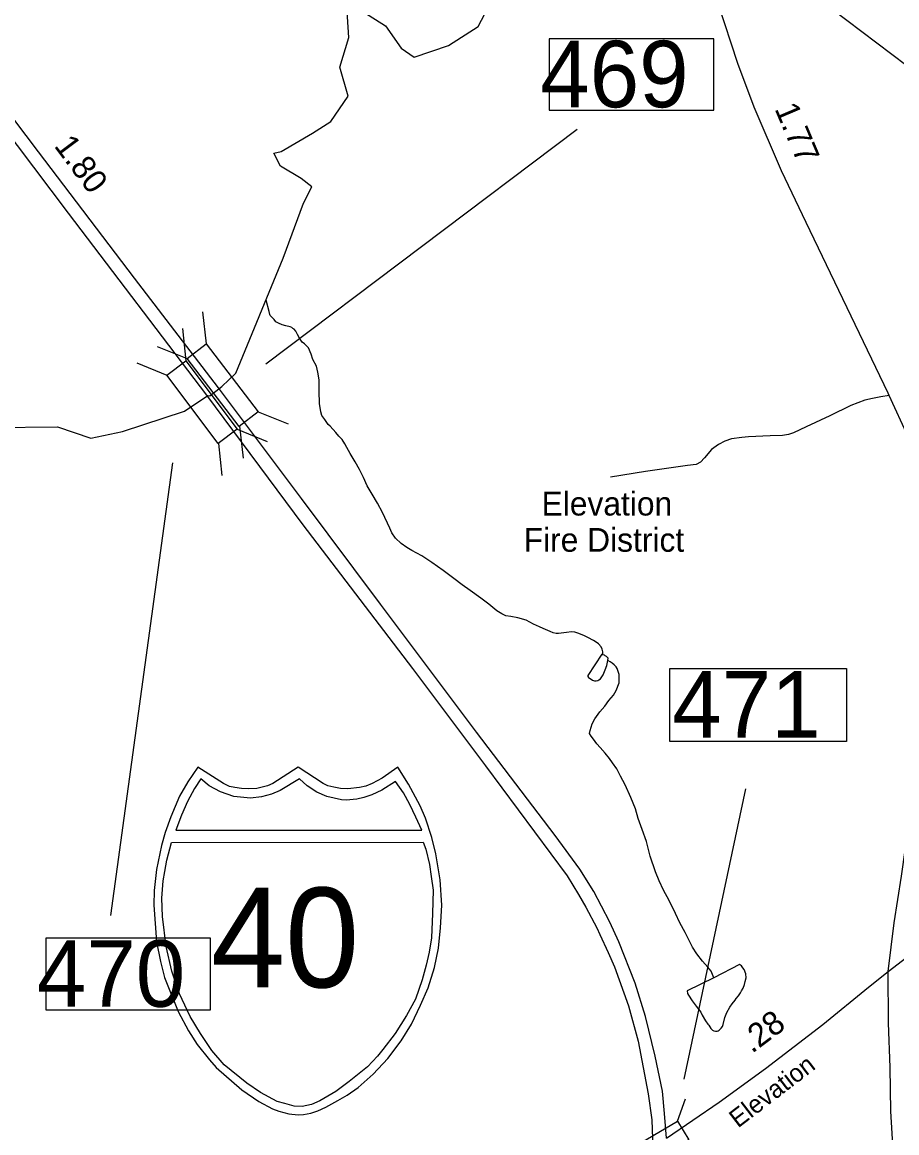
# Model space of a CAD drawing. Extents: x 2082433 to 2279600, y 546599 to 755198.
# Drawn here: x 2135647 to 2140251, y 619052 to 624897 of the extents above; entities that cross this region are included whole.
import ezdxf

# ---------------------------------------------------------------- set-up
doc = ezdxf.new("R2010")
doc.units = 0
for name, color, linetype in [('Exist Boundary Political Fire Districts Label', 7, 'Continuous'), ('Exist Hydrographic Creek Single Shore', 7, 'Continuous'), ('Exist Hydrographic Misc Water Feature', 7, 'Continuous'), ('Exist Hydrographic Pond Under 1500 Sq Ft', 7, 'Continuous'), ('Exist Road Non-System Type 51', 7, 'Continuous'), ('Exist Road Primary Interstate Divided Center Attributed', 7, 'Continuous'), ('Exist Road Primary Interstate Mileage Hundredths English Label', 7, 'Continuous'), ('Exist Road Primary Interstate Shield CELL', 7, 'Continuous'), ('Exist Road Primary Interstate Shield Number Label', 7, 'Continuous'), ('Exist Road Primary Interstate Structure Standard Bridge CELL', 7, 'Continuous'), ('Exist Road Primary Interstate Structure Standard Bridge Number Label', 7, 'Continuous'), ('Exist Road Secondary Mileage Hundredths English Label', 7, 'Continuous'), ('Exist Road Secondary Structure Standard Bridge CELL', 7, 'Continuous'), ('Exist Road Secondary Structure Standard Bridge Number Label', 7, 'Continuous'), ('Exist Road Secondary Type 51 Attributed', 7, 'Continuous'), ('Exist Road Secondary Type 51 Label', 7, 'Continuous')]:
    doc.layers.add(name, color=color, linetype=linetype)

msp = doc.modelspace()

# ---------------------------------------------------------------- linework, layer by layer
at = {"layer": 'Exist Hydrographic Creek Single Shore'}
for points in [[(2137354.5, 625008.9), (2137558.8, 624878.4), (2137641.5, 624761), (2137711, 624713.2), (2137891.2, 624775.6), (2138048.1, 624874.1), (2138139.1, 625049.5), (2138280.2, 625158.1), (2138629.2, 625334.7), (2139152.2, 625531.7), (2139303.2, 625645.9), (2139336.2, 625720.6), (2139444.1, 625770.9), (2139727, 625722.6), (2140152.1, 625776.2), (2140776.1, 625927.6), (2141376.1, 625938.4), (2141684.3, 626040.4), (2141909.2, 625983.4), (2142076.2, 626009.5), (2142267.3, 626159.8), (2142341.3, 626319), (2143015.3, 626371)], [(2137367.5, 624817.6), (2137354.5, 625008.9)], [(2135492, 622764.1), (2135833, 622767), (2136008, 622707.7), (2136175.1, 622743.8), (2136500.9, 622850.7), (2136623.6, 622932.6), (2136634.8, 622930.3), (2136697.4, 622980.7), (2136772.5, 623050.5), (2137021.1, 623655), (2137128, 623944.7), (2137171.8, 624030.5), (2137115.3, 624074), (2137006.6, 624139.2), (2136971.8, 624208.8), (2137011, 624217.5), (2137176.2, 624313.2), (2137271.9, 624374), (2137363.2, 624508.8), (2137319.7, 624661), (2137367.5, 624817.6)], [(2138703.9, 621567.3), (2138704.1, 621583.5), (2138700, 621597.5), (2138694.5, 621609.3), (2138680.1, 621625.2), (2138668, 621635.2), (2138653.7, 621643), (2138623.9, 621658.9), (2138607.9, 621667), (2138578, 621680.9), (2138555.8, 621686.6), (2138538, 621688.5), (2138511.8, 621684.7), (2138469.9, 621680.1), (2138458, 621680.3), (2138442, 621684.3), (2138426, 621690), (2138389.5, 621706.1), (2138369.7, 621716), (2138339.5, 621729.9), (2138299.9, 621749.6), (2138255.4, 621763.3), (2138220, 621769.1), (2138193.3, 621773.1), (2138171.2, 621782.9), (2138145.3, 621799), (2138103.3, 621834.5), (2138061.5, 621866.4), (2138004.7, 621906.3), (2137962.8, 621936.1), (2137918.7, 621969.9), (2137862.8, 622011.7), (2137804.3, 622053.3), (2137750.4, 622089.1), (2137698.1, 622116.9), (2137672.3, 622132.9), (2137642.3, 622154.5), (2137612.2, 622182.6), (2137592.1, 622210.4), (2137581.6, 622234.3), (2137543.5, 622316.3), (2137517.3, 622366.1), (2137489.2, 622413.7), (2137462.9, 622457.8), (2137444.7, 622501.6), (2137422.7, 622543.4), (2137400, 622583.3), (2137374.1, 622627.4), (2137355.7, 622659), (2137345.8, 622679.1), (2137332.1, 622701.1), (2137313.8, 622718.9), (2137297.6, 622738.8), (2137267.7, 622770.9), (2137257.2, 622780.5), (2137239.6, 622806.7), (2137225.1, 622826.8), (2137218.9, 622846.4), (2137212.8, 622890.3), (2137210.7, 622954.7), (2137210.5, 623014.3), (2137204.1, 623056.2), (2137196.1, 623086.3), (2137177.9, 623122.3), (2137168.1, 623150.1), (2137153.7, 623184.3), (2137133.6, 623204), (2137121.7, 623213.9), (2137107.2, 623234), (2137097.3, 623254.1), (2137087.5, 623271.8), (2137079.5, 623282), (2137071.7, 623285.5), (2137067.2, 623289.9), (2137057.3, 623293.8), (2137035.2, 623299.6), (2137015.3, 623305.4), (2136997.2, 623313.4), (2136983.1, 623321.2), (2136973.3, 623333.3), (2136959.1, 623347.2), (2136953.2, 623353.4), (2136950.9, 623359.4), (2136947.2, 623375.4), (2136930.7, 623435.2)], [(2138730.5, 621537.7), (2138730.8, 621549.5), (2138726.7, 621555.4), (2138722.1, 621559.7), (2138716, 621563.4), (2138712.1, 621565.6), (2138703.9, 621567.3)], [(2139287.7, 619868.6), (2139273.7, 619902.3), (2139256.9, 619924.3), (2139229, 619956.1), (2139198.9, 619994.3), (2139175.1, 620029.9), (2139136.1, 620105.6), (2139108.5, 620157.6), (2139086.1, 620205.6), (2139053.5, 620275.4), (2139023.8, 620329), (2138999.4, 620378.9), (2138981.1, 620425.1), (2138953, 620508.8), (2138934.2, 620584.6), (2138910.2, 620648.7), (2138889.9, 620706.5), (2138875.7, 620756.5), (2138851.7, 620816.1), (2138821.4, 620884), (2138797.2, 620929.9), (2138777.1, 620967.8), (2138754.7, 620999.9), (2138739, 621021.8), (2138716.4, 621049.5), (2138690.4, 621079.4), (2138672.3, 621099.6), (2138654.3, 621123.4), (2138642, 621139.5), (2138634.2, 621153.3), (2138636.4, 621169.1), (2138647.9, 621205.5), (2138661.7, 621231.4), (2138687.7, 621267.6), (2138713.5, 621297.8), (2138735.5, 621327.7), (2138759.3, 621355.7), (2138773, 621380), (2138789, 621419.8), (2138790.4, 621443.9), (2138790.4, 621463.8), (2138778.7, 621495.9), (2138774.6, 621503.9), (2138762.5, 621515.8), (2138752.3, 621523.5), (2138742.6, 621531.4), (2138730.5, 621537.7)]]:
    msp.add_lwpolyline(points, dxfattribs=at)
at = {"layer": 'Exist Hydrographic Misc Water Feature'}
msp.add_lwpolyline([(2138703.9, 621567.3), (2138698.4, 621571.4), (2138624.7, 621459.2), (2138624.9, 621453.1), (2138629, 621449.2), (2138632.9, 621445), (2138643, 621439), (2138648.7, 621435.3), (2138659.2, 621431.3), (2138663.1, 621431.2), (2138669, 621431.5), (2138677, 621433.5), (2138682.8, 621435.4), (2138691, 621441.5), (2138704.5, 621463.4), (2138716.6, 621489.5), (2138724.4, 621511.5), (2138728.7, 621529.5), (2138730.5, 621537.7)], dxfattribs=at)
at = {"layer": 'Exist Hydrographic Pond Under 1500 Sq Ft'}
msp.add_lwpolyline([(2139287.7, 619868.6), (2139148.2, 619800), (2139149.7, 619786), (2139154, 619776), (2139174.1, 619746.2), (2139194.2, 619718), (2139207.9, 619702.2), (2139218.6, 619686.4), (2139226.4, 619672.2), (2139244.4, 619642.3), (2139256.7, 619624.6), (2139260.8, 619618.3), (2139272.7, 619600.7), (2139280.7, 619592.6), (2139288.5, 619588.6), (2139296.7, 619586.5), (2139304.7, 619586.5), (2139310.6, 619588.9), (2139316.8, 619592.8), (2139322.5, 619598.8), (2139326.6, 619602.7), (2139333, 619612.6), (2139336.3, 619622.7), (2139346.5, 619658.9), (2139356, 619685), (2139372.2, 619713), (2139384, 619731.1), (2139400.2, 619751), (2139405.8, 619759), (2139417.9, 619773), (2139427.7, 619788.9), (2139433.7, 619799), (2139441.7, 619813.2), (2139449.7, 619833.5), (2139453.6, 619849.1), (2139457.5, 619867.2), (2139455.6, 619889.4), (2139447.4, 619911.3), (2139441.3, 619921.1), (2139433.3, 619931.3), (2139423.2, 619937.2), (2139287.7, 619868.6)], dxfattribs=at)
at = {"layer": 'Exist Road Non-System Type 51'}
msp.add_lwpolyline([(2140211.5, 622932.1), (2140166.1, 622925.7), (2140122.8, 622917), (2140082.1, 622907.4), (2140009, 622880.7), (2139897.6, 622826.1), (2139774.5, 622767), (2139707.8, 622736.2), (2139681.1, 622728.1), (2139648.6, 622722.3), (2139584.8, 622721.1), (2139469.9, 622715.3), (2139435, 622711.8), (2139381.7, 622704.9), (2139345.7, 622693.2), (2139312, 622674.7), (2139276, 622648), (2139238.3, 622604.5), (2139217.4, 622581.2), (2139194.2, 622569.6), (2139148.9, 622563.8), (2138928.4, 622532.5), (2138743.3, 622502.9)], dxfattribs=at)
at = {"layer": 'Exist Road Primary Interstate Divided Center Attributed'}
for points in [[(2134172.6, 627076.6), (2134208, 626913.3), (2134238.4, 626793.1), (2134339.3, 626455.1), (2134482.4, 626062.6), (2134630.3, 625735.3), (2134773.5, 625459.5), (2134919.5, 625215.4), (2135098.9, 624944.4), (2135437.3, 624490.4), (2135890.1, 623892.6), (2136617.6, 622933.6)], [(2136680.9, 622972.7), (2136238.9, 623550.1), (2135732.6, 624215.2), (2135472.1, 624559.5), (2135350.5, 624720.4), (2135081.7, 625091.4), (2134861.3, 625450), (2134677.1, 625802.1), (2134527.6, 626138.9), (2134427.7, 626409.3), (2134319.9, 626760), (2134277.8, 626922.1), (2134238.4, 627096.8)], [(2139039.2, 619023.6), (2139029, 619154.7), (2139018.3, 619271.8), (2138979.7, 619455.3), (2138928.1, 619664.4), (2138874.5, 619839.2), (2138787.6, 620057.9), (2138741.2, 620160.7), (2138697.3, 620244.5), (2138656.3, 620321.8), (2138582.8, 620440.2), (2138452.1, 620617), (2138038.5, 621160.6), (2137533.7, 621835.2), (2137118.2, 622390.2), (2136680.9, 622972.7)], [(2136617.6, 622933.6), (2137123.8, 622252.5), (2137701.2, 621495.5), (2138085.3, 620984.5), (2138515.7, 620404.5), (2138576.1, 620307.2), (2138614.9, 620239.1), (2138671.5, 620131), (2138687.4, 620095.4), (2138732, 620001.2), (2138764.4, 619926.1), (2138838.1, 619720.4), (2138888.9, 619534.7), (2138942.4, 619257.6), (2138961.5, 619119.8), (2138967.5, 618972.2)]]:
    msp.add_lwpolyline(points, dxfattribs=at)
at = {"layer": 'Exist Road Primary Interstate Shield CELL'}
for points in [[(2137099.3, 619146.1), (2137127.7, 619148.8), (2137165.9, 619156.3), (2137203.1, 619168.4), (2137245.4, 619187.2), (2137307.9, 619221.8), (2137358.2, 619251.2), (2137416.2, 619290.2), (2137494.6, 619361.3), (2137572.7, 619443.6), (2137641.7, 619536.8), (2137696.4, 619623.8), (2137744.7, 619723.2), (2137785, 619816), (2137817, 619922), (2137838.1, 620024.7), (2137848.9, 620131.7), (2137856, 620250.5), (2137847.9, 620384.1), (2137824.7, 620520.8), (2137802.9, 620605.8), (2137769.8, 620707.7), (2137742.8, 620772.7), (2137680.3, 620888), (2137624.1, 620976.8), (2137542.4, 620919.3), (2137489.1, 620891), (2137456.6, 620876.3), (2137423.1, 620869.8), (2137361.6, 620862.4), (2137322.9, 620864.1), (2137287.1, 620872.2), (2137256.7, 620878.8), (2137232, 620891), (2137099.3, 620976.8), (2136966.5, 620891), (2136938.6, 620878.2), (2136910.1, 620872.2), (2136882.7, 620864.6), (2136837.2, 620862.4), (2136802.5, 620863.5), (2136766.9, 620869.8), (2136738.8, 620875.7), (2136707.3, 620891), (2136571.9, 620976.8), (2136518.7, 620899.6), (2136475.3, 620823.4), (2136429.2, 620715.6), (2136400.6, 620632.2), (2136380.2, 620563.5), (2136355.1, 620437.7), (2136342.2, 620328), (2136340, 620250.5), (2136354.2, 620056.9), (2136375.3, 619953.8), (2136397, 619870.5), (2136468.6, 619690.4), (2136522.4, 619589.5), (2136568.6, 619517), (2136633.4, 619435.6), (2136668.5, 619396.6), (2136802.9, 619279.1), (2136892.6, 619217.8), (2136964.3, 619179.1), (2136998.1, 619166.3), (2137050.8, 619151.6)], [(2136588, 620914.6), (2136555, 620863.8), (2136517, 620795.3), (2136486.6, 620724.2), (2136455.5, 620645.8), (2137750.2, 620645.3), (2137720.1, 620712.6), (2137687.8, 620780.2), (2137654, 620841.8), (2137612.9, 620901.6), (2137540.3, 620855.8), (2137487.4, 620830.8), (2137444.8, 620816.1), (2137408.9, 620808.1), (2137353.1, 620803.7), (2137328.2, 620805.1), (2137250.4, 620822.8), (2137197.7, 620844.3), (2137147.6, 620877.7), (2137107, 620915.9), (2137004.4, 620853.8), (2136959, 620833.8), (2136906.6, 620820.4), (2136849.4, 620813.2), (2136761.1, 620822.8), (2136691.9, 620846.7), (2136632.2, 620877.7)], [(2137757.8, 620581.4), (2137771.7, 620544.9), (2137790.8, 620463.7), (2137800.8, 620401.2), (2137811.1, 620329.2), (2137807.5, 620205.8), (2137801.5, 620078.1), (2137789.8, 620002.4), (2137774.1, 619933.7), (2137752.6, 619857.3), (2137718, 619755.8), (2137670.3, 619669.8), (2137610.7, 619574.3), (2137546.2, 619490.8), (2137518.2, 619456), (2137465.1, 619400), (2137368.5, 619322.4), (2137297.9, 619269.7), (2137213.4, 619219.8), (2137170.4, 619200.7), (2137120.5, 619190.2), (2137079.4, 619193.1), (2137029.4, 619206.3), (2136989.1, 619217.4), (2136900.8, 619265.1), (2136829.2, 619312.9), (2136709.9, 619410.8), (2136645.6, 619486.1), (2136585.4, 619574.3), (2136531.9, 619664.6), (2136474.6, 619783.6), (2136434.2, 619903.3), (2136404.9, 620032.5), (2136385.1, 620190.4), (2136382.9, 620286.6), (2136388.7, 620379.2), (2136397.5, 620427.6), (2136409.3, 620487.9), (2136432.9, 620580.8)]]:
    msp.add_lwpolyline(points, close=True, dxfattribs=at)
at = {"layer": 'Exist Road Primary Interstate Structure Standard Bridge CELL'}
for p, q in [((2136596.6, 623373.1), (2136615.8, 623204.5)), ((2136491.3, 623284.5), (2136508.8, 623115.7)), ((2136357.6, 623190.2), (2136515.5, 623127.8)), ((2136250.6, 623103.8), (2136407.8, 623039.8)), ((2136889.6, 622846.5), (2137047.4, 622784.1)), ((2136778.8, 622754.8), (2136936, 622690.9)), ((2136791.5, 622771.5), (2136810.7, 622602.9)), ((2136680.1, 622680.7), (2136697.6, 622511.9))]:
    msp.add_line(p, q, dxfattribs=at)
for points in [[(2136615.8, 623204.5), (2136890, 622846.9), (2136789.7, 622770.1), (2136515.5, 623127.8)], [(2136508.8, 623115.7), (2136779.3, 622755.2), (2136678.3, 622679.3), (2136407.8, 623039.8)]]:
    msp.add_lwpolyline(points, close=True, dxfattribs=at)
at = {"layer": 'Exist Road Primary Interstate Structure Standard Bridge Number Label'}
for p, q in [((2136930.2, 623099.2), (2138567.7, 624334.8)), ((2136439, 622578.2), (2136111.5, 620196.4))]:
    msp.add_line(p, q, dxfattribs=at)
for points in [[(2139288, 624809.6), (2138421.5, 624809.6), (2138421.5, 624434), (2139288, 624434)], [(2136638.3, 620075.8), (2135771.8, 620075.8), (2135771.8, 619700.2), (2136638.3, 619700.2)]]:
    msp.add_lwpolyline(points, close=True, dxfattribs=at)
at = {"layer": 'Exist Road Secondary Structure Standard Bridge CELL'}
msp.add_line((2139096.5, 619113.9), (2139137.9, 619231.7), dxfattribs=at)
msp.add_lwpolyline([(2138840.8, 618962), (2139096.3, 619114.3), (2139155.8, 619015), (2138900.3, 618862.7)], close=True, dxfattribs=at)
at = {"layer": 'Exist Road Secondary Structure Standard Bridge Number Label'}
for p, q in [((2139561.8, 625231.2), (2141391.5, 623846.6)), ((2139132, 619333.8), (2139456.1, 620863.4))]:
    msp.add_line(p, q, dxfattribs=at)
msp.add_lwpolyline([(2139056.4, 621496.2), (2139985.4, 621496.2), (2139985.4, 621112.1), (2139056.4, 621112.1)], close=True, dxfattribs=at)
at = {"layer": 'Exist Road Secondary Type 51 Attributed'}
for points in [[(2140205.9, 619901.8), (2140236.6, 620157.6), (2140274.8, 620402.6), (2140334.6, 620825), (2140352.9, 621021.8), (2140375, 621495.5), (2140396.8, 622034.4), (2140403, 622230.6), (2140402, 622300.3), (2140398.1, 622359.8), (2140385.7, 622451.7), (2140368.3, 622540.7), (2140341.6, 622631.1), (2140311.5, 622715.4), (2140211.5, 622932.1), (2140205.5, 622944.7), (2140010, 623350), (2139880.4, 623620.4), (2139773.5, 623843.7), (2139643.8, 624114.7), (2139499.7, 624449.6), (2139414.8, 624680.5), (2139310.7, 624996.4)], [(2140205.9, 619901.8), (2140432.1, 620074.8), (2140730.4, 620326.6), (2141005.1, 620528.9), (2141365.6, 620741.4), (2141994.5, 621092.2), (2142666.8, 621477.5), (2143015.3, 621663.9), (2143383.7, 621828.5)], [(2139039.2, 619023.6), (2139315.5, 619212.8), (2139560.3, 619390.3), (2139861.1, 619623), (2140102.5, 619818.8), (2140205.9, 619901.8)], [(2140236.3, 618873.4), (2140220.4, 619165.8), (2140216.8, 619395.2), (2140207.2, 619630.3), (2140205.9, 619901.8)]]:
    msp.add_lwpolyline(points, dxfattribs=at)

# ---------------------------------------------------------------- texts
at = {"layer": 'Exist Boundary Political Fire Districts Label'}
for s, p in [('Elevation', (2138381.1, 622301)), ('Fire District', (2138286.8, 622110.4))]:
    msp.add_text(s, height=125, dxfattribs=at).set_placement(p)
at = {"layer": 'Exist Road Primary Interstate Mileage Hundredths English Label'}
msp.add_text('1.80', height=125, rotation=306.69678, dxfattribs=at).set_placement((2135811.7, 624245.9))
at = {"layer": 'Exist Road Primary Interstate Shield Number Label'}
msp.add_text('40', height=525, dxfattribs=at).set_placement((2136640.7, 619817.5))
at = {"layer": 'Exist Road Primary Interstate Structure Standard Bridge Number Label'}
for s, p in [('469', (2138374.2, 624449.6)), ('470', (2135724.4, 619715.7))]:
    msp.add_text(s, height=350, dxfattribs=at).set_placement(p)
at = {"layer": 'Exist Road Secondary Mileage Hundredths English Label'}
for s, rotation, p in [('1.77', 292.96941, (2139606.3, 624442.2)), ('.28', 36.93089, (2139488.5, 619467.3))]:
    msp.add_text(s, height=125, rotation=rotation, dxfattribs=at).set_placement(p)
at = {"layer": 'Exist Road Secondary Structure Standard Bridge Number Label'}
msp.add_text('471', height=350, dxfattribs=at).set_placement((2139069, 621131.9))
at = {"layer": 'Exist Road Secondary Type 51 Label'}
msp.add_text('Elevation', height=95, rotation=37.45918, dxfattribs=at).set_placement((2139415, 619074.7))

doc.saveas('drawing.dxf')
